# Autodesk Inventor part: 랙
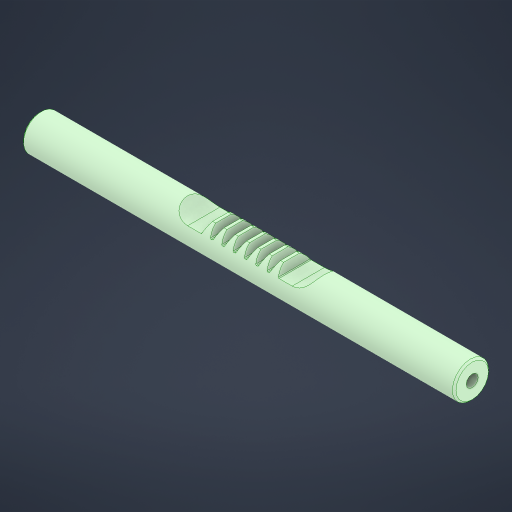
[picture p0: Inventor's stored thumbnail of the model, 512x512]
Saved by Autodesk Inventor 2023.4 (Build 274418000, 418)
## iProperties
Created: 2024-05
Part Number: 랙
Material: 강철, 탄소
Document SubType Name: Modeling
Designer: Edu03
Density: 7.85 g/cm^3
Appearance: 기본값
Sending System: Autodesk Inventor 2025
Preprocessor: ST-DEVELOPER v20
Author: jhkim
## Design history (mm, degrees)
node "랙1"
node "솔리드2"
node "솔리드1"
